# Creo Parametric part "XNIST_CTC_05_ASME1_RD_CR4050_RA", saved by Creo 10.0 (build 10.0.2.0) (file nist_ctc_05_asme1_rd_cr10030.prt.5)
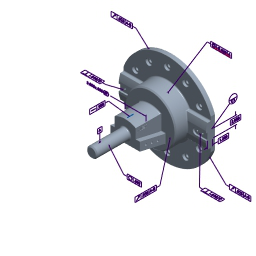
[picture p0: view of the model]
Units: Inch lbm Second (Pro/E Default); INCH, POUND, SECS

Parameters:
  THREAD_SERIES = "UNC"
  SCREW_SIZE = "3/8-16"
  CLASS = "2B"
  METRIC = "NO"
  PART_NUMBER = "NIST PMI CTC 05 ASME1"
  REVISION = "D"
  DESCRIPTION = "NIST PMI test model downloaded from http://go.usa.gov/mGVm"
  PTC_MASTER_MATERIAL = "PTC_SYSTEM_MTRL_PROPS"

Other parameters: DRILL_POINT_ANGLE, DRILL_DEPTH, DRILL_DIAMETER, CBORE_DEPTH, PITCH, THREAD_DIAMETER, THREADS_PER_INCH, THREAD_DEPTH

Created from: NIST_CTC_05_ASME1_RD_CR4050_RA.PRT

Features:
  1. datum plane "RIGHT"
  2. datum plane "TOP"
  3. datum plane "FRONT"
  4. coordinate system
  5. curve
  6. protrusion
  7. curve
  8. protrusion
  9. curve
  10. protrusion
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
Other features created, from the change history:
  sketch "Sketch 14"
  feature "Divide Surface 2"
  datum axis "A_28"

Other named items: CS0, DRF_A-B, AD410, AD413, AD415, GP26, GP27, GP28, DRF2, GP29, GP30, GP31, GP32, DRF3, GP33, DRF4, DT6, DATUM_TAG_A, AD417, DATUM_TAG_B, AD421, AD425, GP34, GP35, DRF5, DT7, DATUM_TAG_D, DATUM_TAG_C, MBD_A, MBD_B, ANNOT_LAYER_STATE0013, ANNOT_LAYER_STATE0014, DEFAULT_LAYER_STATE

Layers: ALL_ANNOTATIONS, ALL_AXES, ALL_CSYS, ALL_CURVES, ALL_PLANES, ALL_POINTS, ALL_QUILTS, DEF_CSYS, DEF_PLANES, MBD_A, MBD_B

Notes:  l| .010 | D | �↗ | .025 | A-B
